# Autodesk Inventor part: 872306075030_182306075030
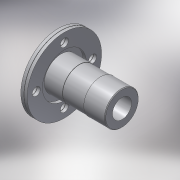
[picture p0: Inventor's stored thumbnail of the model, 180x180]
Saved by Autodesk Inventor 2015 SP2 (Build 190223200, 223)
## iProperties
Created: 2017-02
Part Number: 872306075030_182306075030
Material: PVC-Piping
Description: PLASSON FLANGE ADAPTOR WITH METAL FLANGE 75-3"
Document SubType Name: Modeling
Designer: KIM
Mass: 92.6774 g
Surface Area: 199.44 cm^2
Volume: 66.1981 cm^3
Density: 1.4 g/cm^3
Appearance: Smooth - White
Author: Кирилл
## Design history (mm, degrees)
derived "872306.ipt"
feature "Solid1::872306.ipt"
tag "TaggingFeature1"
body "Solid1"
other parameters: "d73" = 14.2, "d74" = 90 deg, "d75" = 0.3, "d77" = 18, "d80" = 0, "d82" = 360 deg, "d96" = 0.3, "d99" = 360 deg, "d101" = 75, "d103" = 142, "d104" = 1.5, "d107" = 97.5, "d108" = 3.55, "d116" = 73.5, "d117" = 47.33333, "d118" = 47.33333, "d119" = 75, "d120" = 7.5, "d_" = 75, "H_" = 142, "S_" = 18
